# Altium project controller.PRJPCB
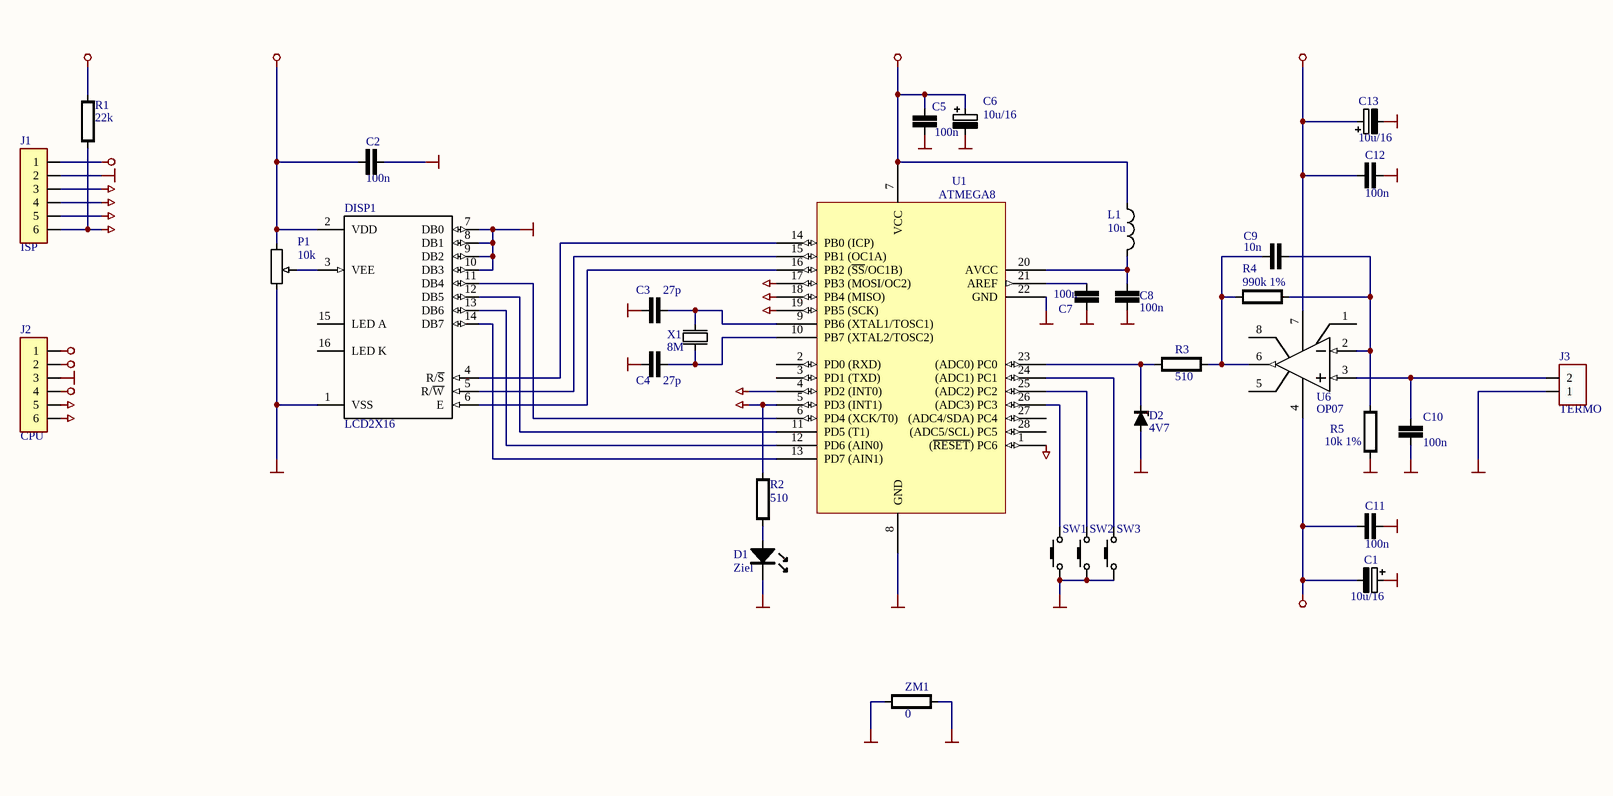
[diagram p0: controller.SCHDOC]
1 sheet, 33 parts. Net scope: global (net labels, ports and power ports of the same name join across sheets).
Board file: controller.PCBDOC

## Sheet controller.SCHDOC: Regulator Temperatury Lutownicy RL1
size B

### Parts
C1  10u/16  [CE5]
C2  100n  [1206]
C3  27p  [1206]
C4  27p  [1206]
C5  100n  [1206]
C6  10u/16  [CE5]
C7  100n  [1206]
C8  100n  [1206]
C9  10n  [1206]
C10  100n  [1206]
C11  100n  [1206]
C12  100n  [1206]
C13  10u/16  [CE5]
D1  Ziel  [LED5]
D2  4V7  [MMELF]
DISP1  LCD2X16  [DTECH162A]
J1  ISP  [ZL6A]
J2  CPU  [ZL6A]
J3  TERMO  [ARK2]
L1  10u  [R3]
P1  10k  [PR3]
R1  22k  [1206]
R2  510  [1206]
R3  510  [1206]
R4  990k 1%  [1206]
R5  10k 1%  [1206]
SW1  SW-PB  [DTS65P]  (value not drawn)
SW2  SW-PB  [DTS65P]  (value not drawn)
SW3  SW-PB  [DTS65P]  (value not drawn)
U1  ATMEGA8  [U28L]
U6  OP07  [SO-G8]
X1  8M  [X2]
ZM1  0  [R1]

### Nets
GND: C2.2 C3.2 C4.2 C5.2 C6.2 D1.2 DISP1.1(VSS) DISP1.7(DB0) DISP1.8(DB1) DISP1.9(DB2) DISP1.10(DB3) J1.2 J2.3 P1.1(UP) SW1.1 SW2.1 SW3.1 U1.8(GND) ZM1.1
GNDA: C1.1 C7.2 C8.2 C10.2 C11.1 C12.1 C13.2 D2.1(A) J3.1 R5.1 U1.22(GND) ZM1.2
GRZ: J2.6 R2.2 U1.5(PD3_(INT1))
M9V: C1.2 C11.2 J2.1 U6.4(V-)
MISO: J1.5 U1.18(PB4_(MISO))
MOSI: J1.4 U1.17(PB3_(MOSI/OC2))
P9V: C12.2 C13.1 J2.2 U6.7(V+)
RST: J1.6 R1.1 U1.1((~{RESET})_PC6)
SCK: J1.3 U1.19(PB5_(SCK))
Vcc: C2.1 C5.1 C6.1 DISP1.2(VDD) J1.1 J2.4 L1.1 P1.3(DWN) R1.2 U1.7(VCC)
ZCD: J2.5 U1.4(PD2_(INT0))
NetC3_1: C3.1 U1.9(PB6_(XTAL1/TOSC1)) X1.2
NetC4_1: C4.1 U1.10(PB7_(XTAL2/TOSC2)) X1.1
NetC7_1: C7.1 U1.21(AREF)
NetC8_1: C8.1 L1.2 U1.20(AVCC)
NetC9_1: C9.1 R4.2 R5.2 U6.2(IN-)
NetC9_2: C9.2 R3.2 R4.1 U6.6(OUT)
NetC10_1: C10.1 J3.2 U6.3(IN+)
NetD1_1: D1.1 R2.1
NetD2_2: D2.2(K) R3.1 U1.23((ADC0)_PC0)
NetDISP1_3: DISP1.3(VEE) P1.2(REG)
NetDISP1_4: DISP1.4(R/~{S}) U1.14(PB0_(ICP))
NetDISP1_5: DISP1.5(R/~{W}) U1.15(PB1_(OC1A))
NetDISP1_6: DISP1.6(E) U1.16(PB2_(~{SS}/OC1B))
NetDISP1_11: DISP1.11(DB4) U1.6(PD4_(XCK/T0))
NetDISP1_12: DISP1.12(DB5) U1.11(PD5_(T1))
NetDISP1_13: DISP1.13(DB6) U1.12(PD6_(AIN0))
NetDISP1_14: DISP1.14(DB7) U1.13(PD7_(AIN1))
NetSW1_2: SW1.2 U1.26((ADC3)_PC3)
NetSW2_2: SW2.2 U1.25((ADC2)_PC2)
NetSW3_2: SW3.2 U1.24((ADC1)_PC1)

Not connected (* = marked no-connect by the designer): DISP1 15(LED_A) 16(LED_K); U1 2(PD0_(RXD)) 3(PD1_(TXD)) 27((ADC4/SDA)_PC4) 28((ADC5/SCL)_PC5); U6 1(VOSTRIM) 5(NC) 8(VOSTRIM)

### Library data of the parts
C1 C6 C13 = EL: Elektrolit
C2-C5 C7-C12 = C: Kondensator
D1 = LED: Dioda LED
D2 = DZ: Dioda Zenera
DISP1 = LCD2X16: Wyswietlacz LCD 2x16
J1 J2 = CON6: Z彻cze 6
J3 = CON2: Z彻cze ARK2
L1 = L: Cewka
P1 = POT: Potencjometr
R1-R5 ZM1 = R: Rezystor
SW1-SW3 = SW-PB: Mikroswitch
U1 = ATMEGA8_DIP28: Atmel Microcontroller - Library created by carel..  <www.mpfreezone.com>
U6 = OP07: Ultra-Low Offset Voltage Operational Amplifier; Manufacturer: Analog Devices; Note: Pin 5 is not connected.
X1 = XTAL: Crystal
